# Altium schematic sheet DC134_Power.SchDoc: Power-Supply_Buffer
size 431 x 279 mm; Date: Not shown in title block; ApprovedBy: Not shown in title block; CheckedBy: Not shown in title block; Author: Not shown in title block; CompanyName: Not shown in title block; DrawnBy: Daniel Brock; Engineer: Not shown in title block; Organization: Not shown in title block; Address1: Not shown in title block; Address2: Not shown in title block; Address3: Not shown in title block; Address4: Not shown in title block; DocumentNumber: 6; Revision: Use project parameter SCH_Rev; SheetNumber: 6; SheetTotal: 9; PageSetup: Record=PageOptions¦CenterHorizontal=True¦CenterVertical=True¦PrintScale=1.00¦XCorrection=1.00¦YCorrection=1.00¦PrintKind=0¦BorderSize=5000000¦LeftOffset=0¦BottomOffset=0¦Orientation=2¦PaperLength=1000¦PaperWidth=1000¦Scale=100¦PaperSource=15¦PrintQuality=600¦MediaType=1¦DitherType=10¦PaperKind=Letter¦PrintScaleMode=1
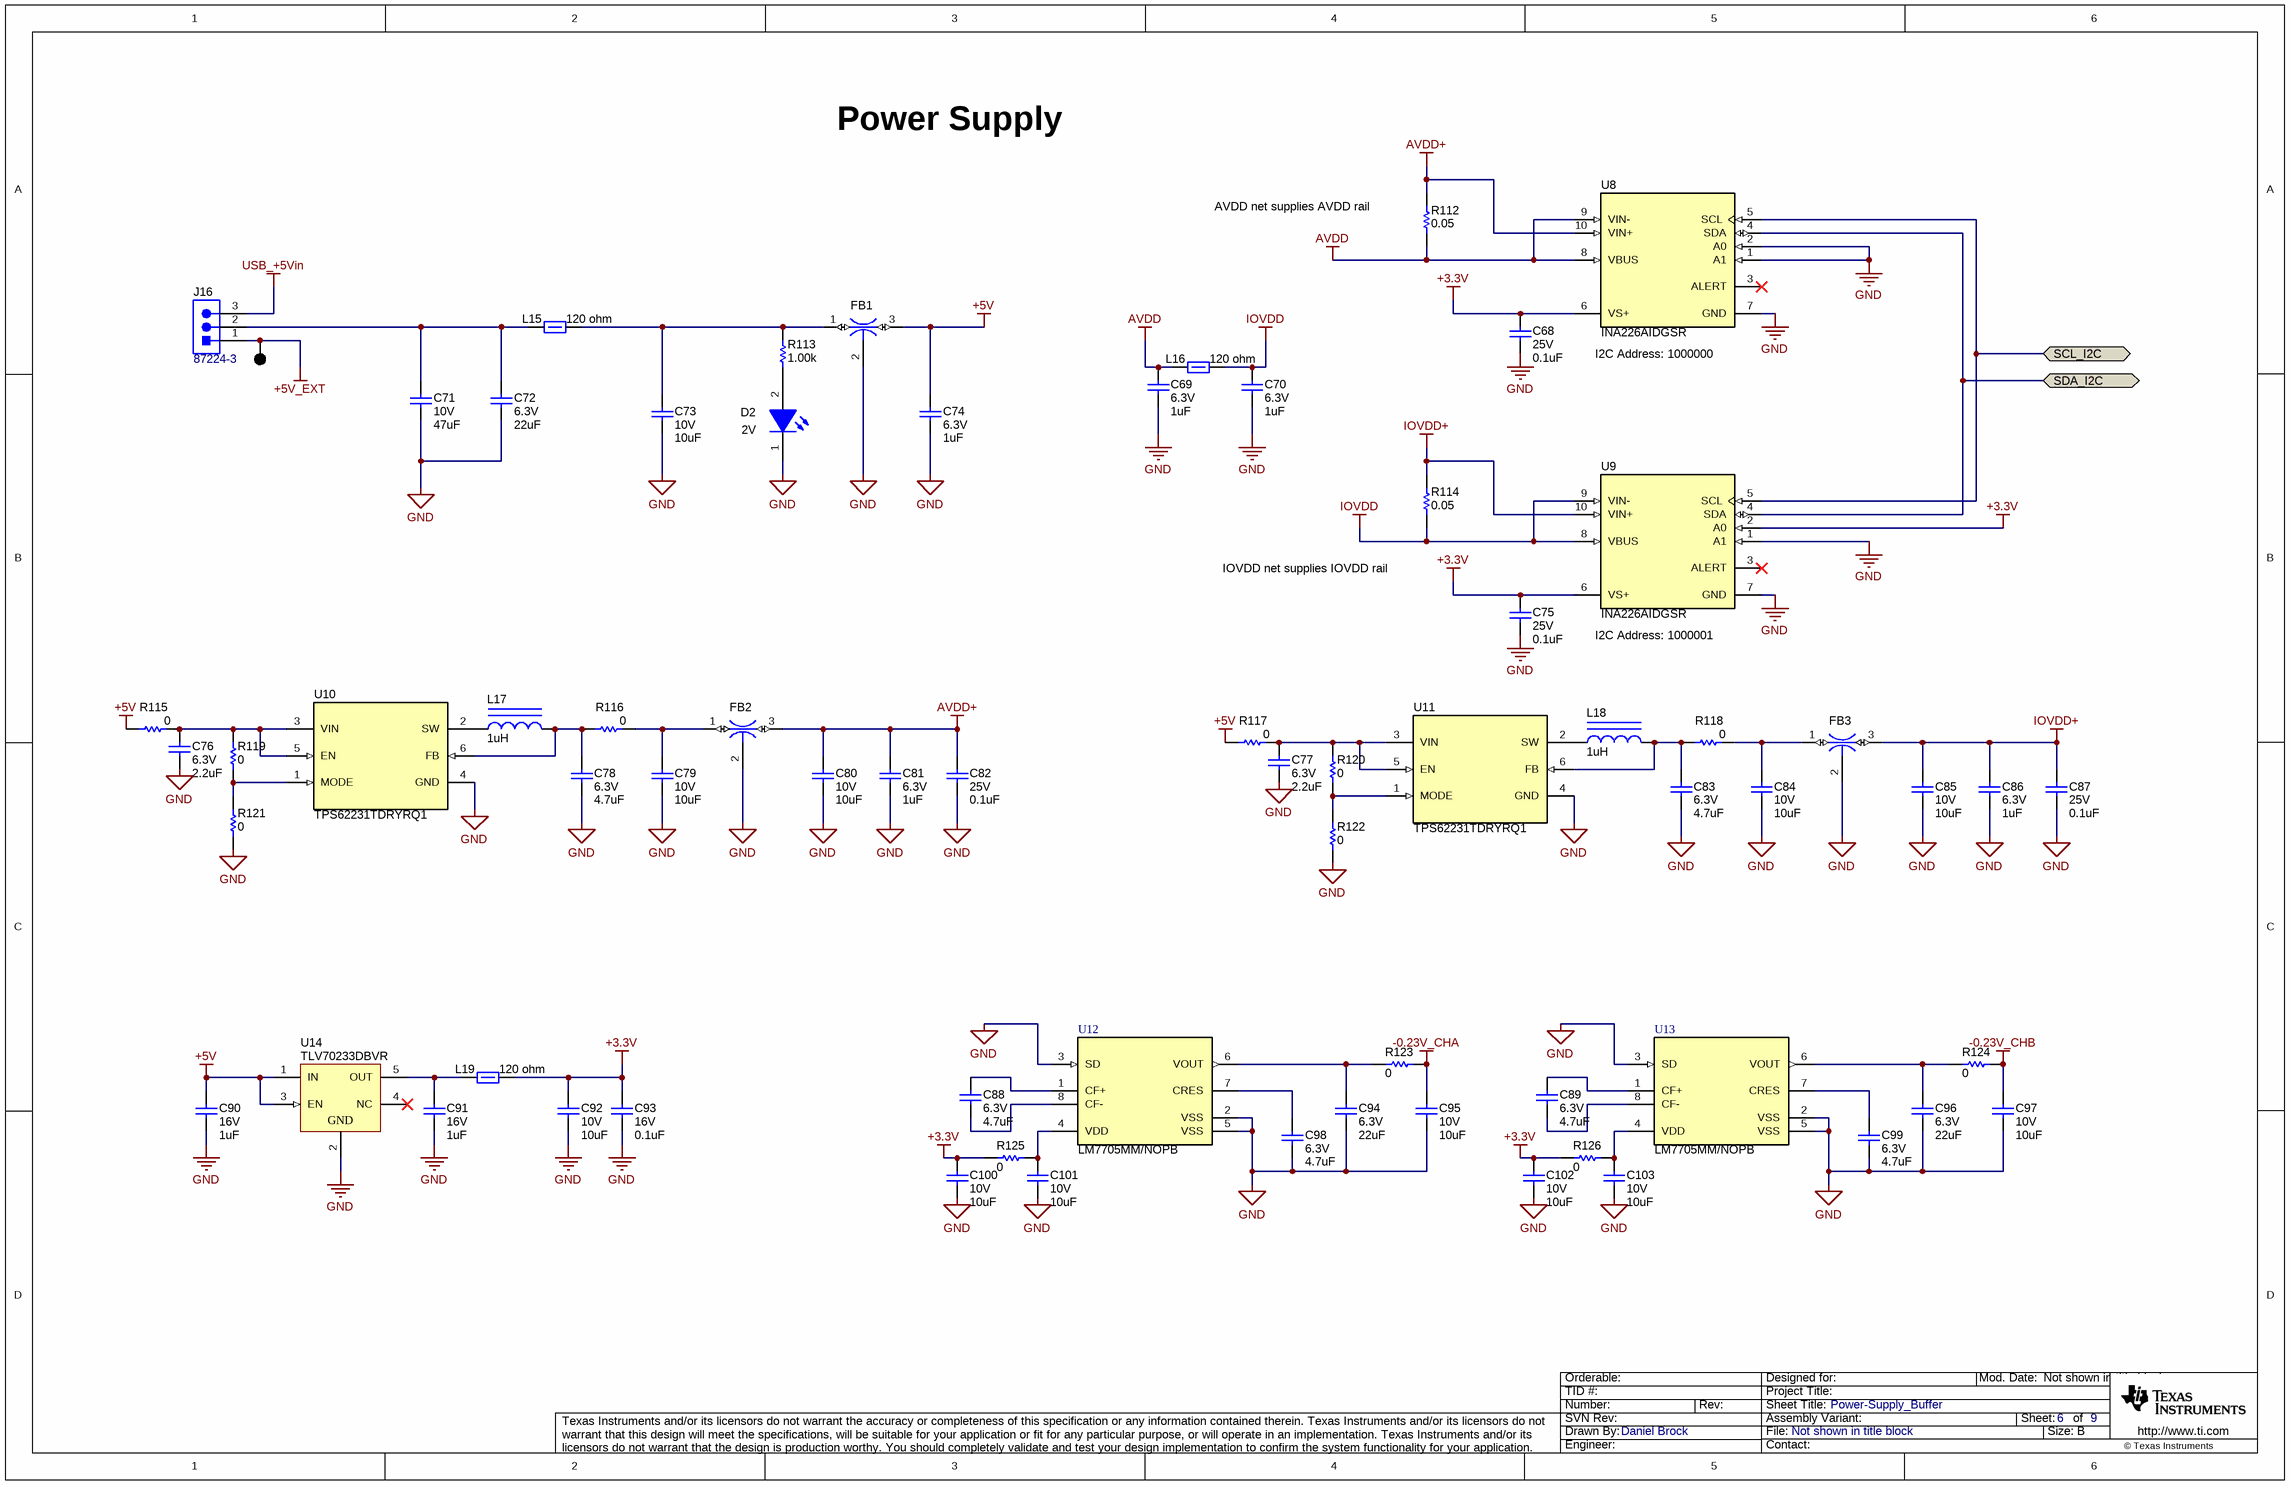
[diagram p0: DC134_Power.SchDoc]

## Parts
+1  5011  [Keystone5011]  (value not drawn)
C68  VDC_V: 25V  ValueDisplayed: 0.1uF  [0402]  (hidden comment: GRM155R61E104KA87D)
C69  VDC_V: 6.3V  ValueDisplayed: 1uF  [0402]  (hidden comment: GRM152R60J105ME15D)
C70  VDC_V: 6.3V  ValueDisplayed: 1uF  [0402]  (hidden comment: GRM152R60J105ME15D)
C71  VDC_V: 10V  ValueDisplayed: 47uF  [1210_270]  (hidden comment: GRM32ER61A476KE20L)
C72  VDC_V: 6.3V  ValueDisplayed: 22uF  [0805_HV]  (hidden comment: JMK212BJ226MG-T)
C73  VDC_V: 10V  ValueDisplayed: 10uF  [0603]  (hidden comment: GRM188R61A106ME69D)
C74  VDC_V: 6.3V  ValueDisplayed: 1uF  [0402]  (hidden comment: GRM152R60J105ME15D)
C75  VDC_V: 25V  ValueDisplayed: 0.1uF  [0402]  (hidden comment: GRM155R61E104KA87D)
C76  VDC_V: 6.3V  ValueDisplayed: 2.2uF  [0402]  (hidden comment: GRM155R60J225ME15D)
C77  VDC_V: 6.3V  ValueDisplayed: 2.2uF  [0402]  (hidden comment: GRM155R60J225ME15D)
C78  VDC_V: 6.3V  ValueDisplayed: 4.7uF  [0603]  (hidden comment: C0603C475K9PACTU)
C79  VDC_V: 10V  ValueDisplayed: 10uF  [0603]  (hidden comment: GRM188R61A106ME69D)
C80  VDC_V: 10V  ValueDisplayed: 10uF  [0603]  (hidden comment: GRM188R61A106ME69D)
C81  VDC_V: 6.3V  ValueDisplayed: 1uF  [0402]  (hidden comment: GRM152R60J105ME15D)
C82  VDC_V: 25V  ValueDisplayed: 0.1uF  [0201_033]  (hidden comment: GRM033R61E104KE14J)
C83  VDC_V: 6.3V  ValueDisplayed: 4.7uF  [0603]  (hidden comment: C0603C475K9PACTU)
C84  VDC_V: 10V  ValueDisplayed: 10uF  [0603]  (hidden comment: GRM188R61A106ME69D)
C85  VDC_V: 10V  ValueDisplayed: 10uF  [0603]  (hidden comment: GRM188R61A106ME69D)
C86  VDC_V: 6.3V  ValueDisplayed: 1uF  [0402]  (hidden comment: GRM152R60J105ME15D)
C87  VDC_V: 25V  ValueDisplayed: 0.1uF  [0201_033]  (hidden comment: GRM033R61E104KE14J)
C88  VDC_V: 6.3V  ValueDisplayed: 4.7uF  [0603]  (hidden comment: C0603C475K9PACTU)
C89  VDC_V: 6.3V  ValueDisplayed: 4.7uF  [0603]  (hidden comment: C0603C475K9PACTU)
C90  VDC_V: 16V  ValueDisplayed: 1uF  [0603]  (hidden comment: 885012206052)
C91  VDC_V: 16V  ValueDisplayed: 1uF  [0603]  (hidden comment: 885012206052)
C92  VDC_V: 10V  ValueDisplayed: 10uF  [0805_HV]  (hidden comment: 885012207026)
C93  VDC_V: 16V  ValueDisplayed: 0.1uF  [0201L]  (hidden comment: GRM033Z71C104KE14D)
C94  VDC_V: 6.3V  ValueDisplayed: 22uF  [0805_HV]  (hidden comment: JMK212BJ226MG-T)
C95  VDC_V: 10V  ValueDisplayed: 10uF  [0805_HV]  (hidden comment: 885012207026)
C96  VDC_V: 6.3V  ValueDisplayed: 22uF  [0805_HV]  (hidden comment: JMK212BJ226MG-T)
C97  VDC_V: 10V  ValueDisplayed: 10uF  [0805_HV]  (hidden comment: 885012207026)
C98  VDC_V: 6.3V  ValueDisplayed: 4.7uF  [0603]  (hidden comment: C0603C475K9PACTU)
C99  VDC_V: 6.3V  ValueDisplayed: 4.7uF  [0603]  (hidden comment: C0603C475K9PACTU)
C100  VDC_V: 10V  ValueDisplayed: 10uF  [0805_HV]  (hidden comment: 885012207026)
C101  VDC_V: 10V  ValueDisplayed: 10uF  [0805_HV]  (hidden comment: 885012207026)
C102  VDC_V: 10V  ValueDisplayed: 10uF  [0805_HV]  (hidden comment: 885012207026)
C103  VDC_V: 10V  ValueDisplayed: 10uF  [0805_HV]  (hidden comment: 885012207026)
D2  Value2: 2V  [LTST-C150_1206_Green]  (hidden comment: LTST-C150KGKT)
FB1  NFM31PC276B0J3L  [Murata_NFM31P]  (value not drawn)
FB2  NFM31PC276B0J3L  [Murata_NFM31P]  (value not drawn)
FB3  NFM31PC276B0J3L  [Murata_NFM31P]  (value not drawn)
J16  87224-3  [TE_87224-3]
L15  ValueDisplayed: 120 ohm  [0402]  (hidden comment: 74279271)
L16  ValueDisplayed: 120 ohm  [0402]  (hidden comment: 74279271)
L17  ValueDisplayed: 1uH  [0805_HV]  (hidden comment: LQM21PN1R0MC0D)
L18  ValueDisplayed: 1uH  [0805_HV]  (hidden comment: LQM21PN1R0MC0D)
L19  ValueDisplayed: 120 ohm  [0402]  (hidden comment: 74279271)
R112  ValueDisplayed: 0.05  [0603]  (hidden comment: ERJ-L03KF50MV)
R113  ValueDisplayed: 1.00k  [0402]  (hidden comment: RC0402FR-071KL)
R114  ValueDisplayed: 0.05  [0603]  (hidden comment: ERJ-L03KF50MV)
R115  value 0  [0402]  (hidden comment: Resistor)
R116  value 0  [0402]  (hidden comment: Resistor)
R117  value 0  [0402]  (hidden comment: Resistor)
R118  value 0  [0402]  (hidden comment: Resistor)
R119  value 0  [0402]  (hidden comment: Resistor)
R120  value 0  [0402]  (hidden comment: Resistor)
R121  value 0  [0402]  (hidden comment: Resistor)
R122  value 0  [0402]  (hidden comment: Resistor)
R123  ValueDisplayed: 0  [0402]  (hidden comment: RK73Z1ETTP)
R124  ValueDisplayed: 0  [0402]  (hidden comment: RK73Z1ETTP)
R125  ValueDisplayed: 0  [0402]  (hidden comment: RK73Z1ETTP)
R126  ValueDisplayed: 0  [0402]  (hidden comment: RK73Z1ETTP)
U8  INA226AIDGSR  [DGS0010A_L]
U9  INA226AIDGSR  [DGS0010A_L]
U10  TPS62231TDRYRQ1  [DRY0006A]
U11  TPS62231TDRYRQ1  [DRY0006A]
U12  LM7705MM/NOPB  [DGK0008A_N]
U13  LM7705MM/NOPB  [DGK0008A_N]
U14  TLV70233DBVR  [DBV0005A_N]

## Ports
SCL_I2C (bidir), SDA_I2C (bidir)

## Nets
+3.3V: C68.1 C75.1 C92.1 C93.2 C100.1 C102.1 L19.2 R125.1 R126.1 U8.6(VS+) U9.2(A0) U9.6(VS+)
+5V: C74.1 C90.1 FB1.3 R115.1 R117.1 U14.1(IN) U14.3(EN)
+5V_EXT: +1.+5V_EXT J16.1
-0.23V_CHA: C95.1 R123.2
-0.23V_CHB: C97.1 R124.2
AVDD: C69.1 L16.1 R112.1 U8.8(VBUS) U8.9(VIN-)
AVDD+: C80.1 C81.1 C82.1 FB2.3 R112.2 U8.10(VIN+)
GND: C68.2 C69.2 C70.2 C71.2 C72.2 C73.2 C74.2 C75.2 C76.2 C77.2 C78.2 C79.2 C80.2 C81.2 C82.2 C83.2 C84.2 C85.2 C86.2 C87.2 C90.2 C91.2 C92.2 C93.1 C94.2 C95.2 C96.2 C97.2 C98.2 C99.2 C100.2 C101.2 C102.2 C103.2 D2.1(K) FB1.2 FB2.2 FB3.2 R121.1 R122.1 U8.1(A1) U8.2(A0) U8.7(GND) U9.1(A1) U9.7(GND) U10.4(GND) U11.4(GND) U12.2(VSS) U12.3(SD) U12.5(VSS) U13.2(VSS) U13.3(SD) U13.5(VSS) U14.2(GND)
IOVDD: C70.1 L16.2 R114.1 U9.8(VBUS) U9.9(VIN-)
IOVDD+: C85.1 C86.1 C87.1 FB3.3 R114.2 U9.10(VIN+)
USB_+5Vin: J16.3
SCL_I2C: U8.5(SCL) U9.5(SCL) ; port SCL_I2C
SDA_I2C: U8.4(SDA) U9.4(SDA) ; port SDA_I2C
NetC71_1: C71.1 C72.1 J16.2 L15.1
NetC73_1: C73.1 FB1.1 L15.2 R113.2
NetC76_1: C76.1 R115.2 R119.2 U10.3(VIN) U10.5(EN)
NetC77_1: C77.1 R117.2 R120.2 U11.3(VIN) U11.5(EN)
NetC78_1: C78.1 L17.2 R116.1 U10.6(FB)
NetC79_1: C79.1 FB2.1 R116.2
NetC83_1: C83.1 L18.2 R118.1 U11.6(FB)
NetC84_1: C84.1 FB3.1 R118.2
NetC88_1: C88.1 U12.1(CF+)
NetC88_2: C88.2 U12.8(CF-)
NetC89_1: C89.1 U13.1(CF+)
NetC89_2: C89.2 U13.8(CF-)
NetC91_1: C91.1 L19.1 U14.5(OUT)
NetC94_1: C94.1 R123.1 U12.6(VOUT)
NetC96_1: C96.1 R124.1 U13.6(VOUT)
NetC98_1: C98.1 U12.7(CRES)
NetC99_1: C99.1 U13.7(CRES)
NetC101_1: C101.1 R125.2 U12.4(VDD)
NetC103_1: C103.1 R126.2 U13.4(VDD)
NetD2_2: D2.2(A) R113.1
NetL17_1: L17.1 U10.2(SW)
NetL18_1: L18.1 U11.2(SW)
NetR119_1: R119.1 R121.2 U10.1(MODE)
NetR120_1: R120.1 R122.2 U11.1(MODE)

Not connected (* = marked no-connect by the designer): U8 3(ALERT)*; U9 3(ALERT)*; U14 4(NC)*

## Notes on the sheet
- Power Supply
- (near R112) AVDD net supplies AVDD rail
- (near U8) I2C Address: 1000000
- IOVDD net supplies IOVDD rail
- (near U9) I2C Address: 1000001

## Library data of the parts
+1 = CMP-0055148-1: Test Point, Multipurpose, Black, TH; Manufacturer: Keystone; CNHeader: FALSE; Green_Lifecycle: Active; Green_REACh: Passed; ContactFinish: Silver; CT: TRUE
C68 C75 = CMP-0006607-2: CAP, CERM, 0.1 uF, 25 V, +/- 10%, X5R, 0402; Manufacturer: MuRata; TaMin_C: -55°C; Polarized: N; SizeAreaWB_mm2: 3; Value1: Unknown; U/M: EA; Value: 0.1uF; TaMax_C: 85°C; SizeZ_mm: 0.6; SizeX_mm: 1; SizeY_mm: 0.5; Cap_F: 100nF; AEC Category: Q200
C69 C70 C74 C81 C86 = CMP-0006372-2: CAP, CERM, 1 uF, 6.3 V, +/- 20%, X5R, 0402; Manufacturer: MuRata; TaMin_C: -55°C; Polarized: N; SizeAreaWB_mm2: 3; Value1: Unknown; U/M: EA; Value: 1uF; TaMax_C: 85°C; SizeZ_mm: 0.6; SizeX_mm: 1; SizeY_mm: 0.5; Cap_F: 1µF; AEC Category: Q200
C71 = CMP-0009208-2: CAP, CERM, 47 uF, 10 V, +/- 10%, X5R, 1210; Manufacturer: MuRata; TaMin_C: -55°C; ESR_ohm: 1m; Polarized: N; SizeAreaWB_mm2: 14.7; Value1: 0.001 ohm; U/M: EA; Value: 47uF; TaMax_C: 85°C; SizeZ_mm: 2.7; SizeX_mm: 3.2; SizeY_mm: 2.5; Cap_Case: 1210; SizeArea_mm2: 8; Cap_F: 47µF; AEC Category: Q200
C72 C94 C96 = CMP-0008391-2: CAP, CERM, 22 uF, 6.3 V, +/- 20%, X5R, 0805; Manufacturer: Taiyo Yuden; TaMin_C: -55°C; Polarized: N; SizeAreaWB_mm2: 6.75; Value1: Unknown; U/M: EA; Value: 22uF; TaMax_C: 85°C; SizeZ_mm: 1.45; SizeX_mm: 2; SizeY_mm: 1.25; Cap_Case: 0805; SizeArea_mm2: 2.5; Cap_F: 22µF; AEC Category: Q200
C73 C79 C80 C84 C85 = CMP-0007318-5: CAP, CERM, 10 uF, 10 V, +/- 20%, X5R, 0603; Manufacturer: MuRata; TaMin_C: -55°C; Polarized: N; SizeAreaWB_mm2: 4.68; Value1: Unknown; U/M: EA; Value: 10uF; TaMax_C: 85°C; SizeZ_mm: 1; SizeX_mm: 1.6; SizeY_mm: 0.8; SizeArea_mm2: 1.28; Cap_F: 10µF; AEC Category: Q200
C76 C77 = CMP-0006544-2: CAP, CERM, 2.2 uF, 6.3 V, +/- 20%, X5R, 0402; Manufacturer: MuRata; TaMin_C: -55°C; ESR_ohm: 5m; Polarized: N; SizeAreaWB_mm2: 3; Value1: 0.005 ohm; U/M: EA; Value: 2.2uF; TaMax_C: 125°C; SizeZ_mm: 0.6; SizeX_mm: 1; SizeY_mm: 0.5; Cap_F: 2.2µF; IRMS_A: 3.67A; AEC Category: Q200
C78 C83 C88 C89 C98 C99 = CMP-0006950-5: CAP, CERM, 4.7 uF, 6.3 V, +/- 10%, X5R, 0603; Manufacturer: Kemet; TaMin_C: -55°C; ESR_ohm: 6m; Polarized: N; SizeAreaWB_mm2: 4.68; Value1: 0.006 ohm; U/M: EA; Value: 4.7uF; TaMax_C: 85°C; SizeZ_mm: 1; SizeX_mm: 1.6; SizeY_mm: 0.8; SizeArea_mm2: 1.28; Cap_F: 4.7µF; IRMS_A: 7.24A; AEC Category: Q200
C82 C87 = CMP-0009719-2: CAP, CERM, 0.1 uF, 25 V, +/- 10%, X5R, 0201; Manufacturer: MuRata; TaMin_C: -55°C; Polarized: N; SizeAreaWB_mm2: 2.08; Value1: Unknown; U/M: EA; Value: 0.1uF; TaMax_C: 85°C; SizeZ_mm: 0.33; SizeX_mm: 0.6; SizeY_mm: 0.3; Cap_Case: 0201; SizeArea_mm2: 0.18; Cap_F: 100nF; AEC Category: Q200
C90 C91 = CMP-0006831-4: CAP, CERM, 1 uF, 16 V, +/- 10%, X7R, 0603; Manufacturer: Wurth Elektronik; TaMin_C: -55°C; Polarized: N; SizeAreaWB_mm2: 4.68; Value1: Unknown; U/M: EA; Value: 1uF; TaMax_C: 125°C; SizeZ_mm: 1; SizeX_mm: 1.6; SizeY_mm: 0.8; SizeArea_mm2: 1.28; Cap_F: 1µF; AEC Category: Q200
C92 C95 C97 C100-C103 = CMP-0007691-2: CAP, CERM, 10 uF, 10 V, +/- 10%, X7R, 0805; Manufacturer: Wurth Elektronik; TaMin_C: -55°C; Polarized: N; SizeAreaWB_mm2: 6.75; Value1: Unknown; U/M: EA; Value: 10uF; TaMax_C: 125°C; SizeZ_mm: 1.45; SizeX_mm: 2; SizeY_mm: 1.25; Cap_Case: 0805; SizeArea_mm2: 2.5; Cap_F: 10µF; AEC Category: Q200
C93 = CMP-0064970-1: CAP, CERM, 0.1 uF, 16 V,+/- 10%, X7R, 0201; Manufacturer: MuRata; TaMin_C: -55°C; Polarized: N; SizeAreaWB_mm2: 2.08; Value1: Unknown; U/M: EA; Value: 0.1uF; TaMax_C: 125°C; SizeZ_mm: 0.26; SizeX_mm: 0.6; SizeY_mm: 0.3; Cap_Case: 0201; SizeArea_mm2: 0.18; Cap_F: 100nF; AEC Category: Q200
D2 = CMP-0002920-2: LED, Green, SMD; Manufacturer: LiteOn; Io_A: 30mA; Vr_V: 5V; Tjmax_C: 85°C; Value1: W; Angle: 130; Type: AlInGaP
FB1-FB3 = CMP-0001934-2: FILTER LC HIGH FREQ 27uF 1206; Manufacturer: MuRata
J16 = CMP-0078139-1: Header, 2.54mm, 3x1, Gold, TH; Manufacturer: TE Connectivity; Pitch_mm: 2.54; Gender: Male; Cert_UL: Y; Current_A: 3A; Voltage_V: 750V; Green_REACh: Passed; Shrouded: N; Green_Lifecycle: Active; Row_Count: 1
L15 L16 L19 = CMP-0003214-1: Ferrite Bead, 120 ohm @ 100 MHz, 0.5 A, 0402; Manufacturer: Wurth Elektronik; Ztyp@1GHz_Ohm: 175.42; ZTyp@100MHz_Ohm: 120; SizeAreaWB_mm2: 3; DCR_ohm: 2d; Value1: 0.2 ohm; Value: 120 ohm; Imax_A: 5dA; SizeZ_mm: 0.6; SizeX_mm: 1; SizeY_mm: 0.5; Value2: 0.5A
L17 L18 = CMP-0058739-1: Inductor, Multilayer, Ferrite, 1 uH, 0.8 A, 0.19 ohm, SMD; Manufacturer: MuRata; Irms: 0.8A @ 40C rise; Green_Lifecycle: Active; SizeAreaWB_mm2: 6.75; DCR_ohm: 0.19; Green_REACh: Passed; Value: 1uH; Imax_A: 800mA; SizeZ_mm: 1.45; SizeX_mm: 2; SizeY_mm: 1.25; Value2: 0.8A; SizeArea_mm2: 2.5; Ind_H: 1µH; AEC Category: Q200
R112 R114 = CMP-0022727-3: RES, 0.05, 1%, 0.1 W, AEC-Q200 Grade 1, 0603; Manufacturer: Panasonic; Power_W: 100mW; TempCo: 200 ppm/C; Value_Code: R050; Value: 0.05; EIA_Code: E96; SizeX_mm: 1.6; SizeY_mm: 0.8; SizeZ_mm: 1; Value2: 0.1W; SizeArea_mm2: 1.28; AEC Qualified: Y; AEC Category: Q200; SizeAreaWB_mm2: 4.68
R113 = CMP-0026725-1: RES, 1.00 k, 1%, 0.0625 W, 0402; Manufacturer: Yageo America; Power_W: 62.5mW; TempCo: 100 ppm/C; Value_Code: 1k00; U/M: EA; Value: 1.00k; EIA_Code: E96; Res_ohm: 1k; SizeX_mm: 1; SizeY_mm: 0.5; SizeZ_mm: 0.6; AEC Qualified: N; VDC_V: 50V; AEC Category: Q200
R115-R122 = CMP-0026822-3: RES, 0, 5%, 0.063 W, AEC-Q200 Grade 0, 0402; Manufacturer: Vishay-Dale; PartNumber: CRCW04020000Z0ED; Value_Code: 0000; Power_W: 63mW; Value2: 0.063W; VDC_V: 50V; TempCo: 200 ppm/C; EIA_Code: E24; AEC Category: Q200; AEC Qualified: Y; SizeArea_mm2: 0.5; SizeX_mm: 1; SizeZ_mm: 0.6
R123-R126 = CMP-0027007-2: RES, 0, 5%, 0.063 W, AEC-Q200 Grade 0, 0402; Manufacturer: KOA Speer; Power_W: 63mW; TempCo: ppm/C; Value_Code: 0000; U/M: EA; Value: 0; EIA_Code: E24; SizeX_mm: 1; SizeY_mm: 0.5; SizeZ_mm: 0.6; Value2: 0.063W; AEC Qualified: Y; AEC Category: Q200
U8 U9 = CMP-0037979-1: High-Side Measurement, Bi-Directional Current / Power Monitor with I2C Interface, 2.7 to 5.5 V, -40 to 125 degC, 10-pin SOP (DGS10), Green (RoHS & no Sb/Br); Common Mode Range(Max)(V): 36; Vs(Min)(V): 2.7; SubFamily: Current Shunt Monitor; Small-Signal Bandwidth(Typ)(MHz): 0.007; CMRR(Min)(dB): 126; Gain(V/V): 1; Vs(Max)(V): 5.5; Rating: Catalog; Input Offset Drift (+/-)(Max)(uV/Degrees Celsius): 0.1; Quiescent Current (+/-)(Typ)(mA): 0.33; Common Mode Range(Min)(V): 0; Input Offset (+/-)(Max)(uV): 10
U10 U11 = CMP-0074035-3: Automotive 2V to 6V, 500mA Buck Converter with 1.8V Fixed Output Voltage in 1x1.5mm SON Package, DRY0006A (USON-6); Manufacturer: Texas Instruments; SizeAreaWB_mm2: 4.9; SizeZ_mm: 0.6; SizeX_mm: 1.0; SizeY_mm: 1.45; CompType: IC; AEC Category: Q200; AEC Qualified: Y
U12 U13 = CMP-0072065-2: Low Noise Negative Bias Generator, 8-pin Mini SOIC, Pb-Free; Manufacturer: Texas Instruments; CompType: IC; PowerWise: N
U14 = CMP-0035516-1: Single Output LDO, 300 mA, Fixed 3.3 V Output, 2 to 5.5 V Input, with Low IQ, 5-pin SOT-23 (DBV), -40 to 125 degC, Green (RoHS & no Sb/Br); Manufacturer: Texas Instruments; Fixed Output Options(V): 3.3; Vdo(Typ)(mV): 220; Accuracy(%): 2; Iq(Typ)(mA): 0.03; SubFamily: Single Channel LDO; Iout(Max)(A): 0.3; Vin(Max)(V): 5.5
